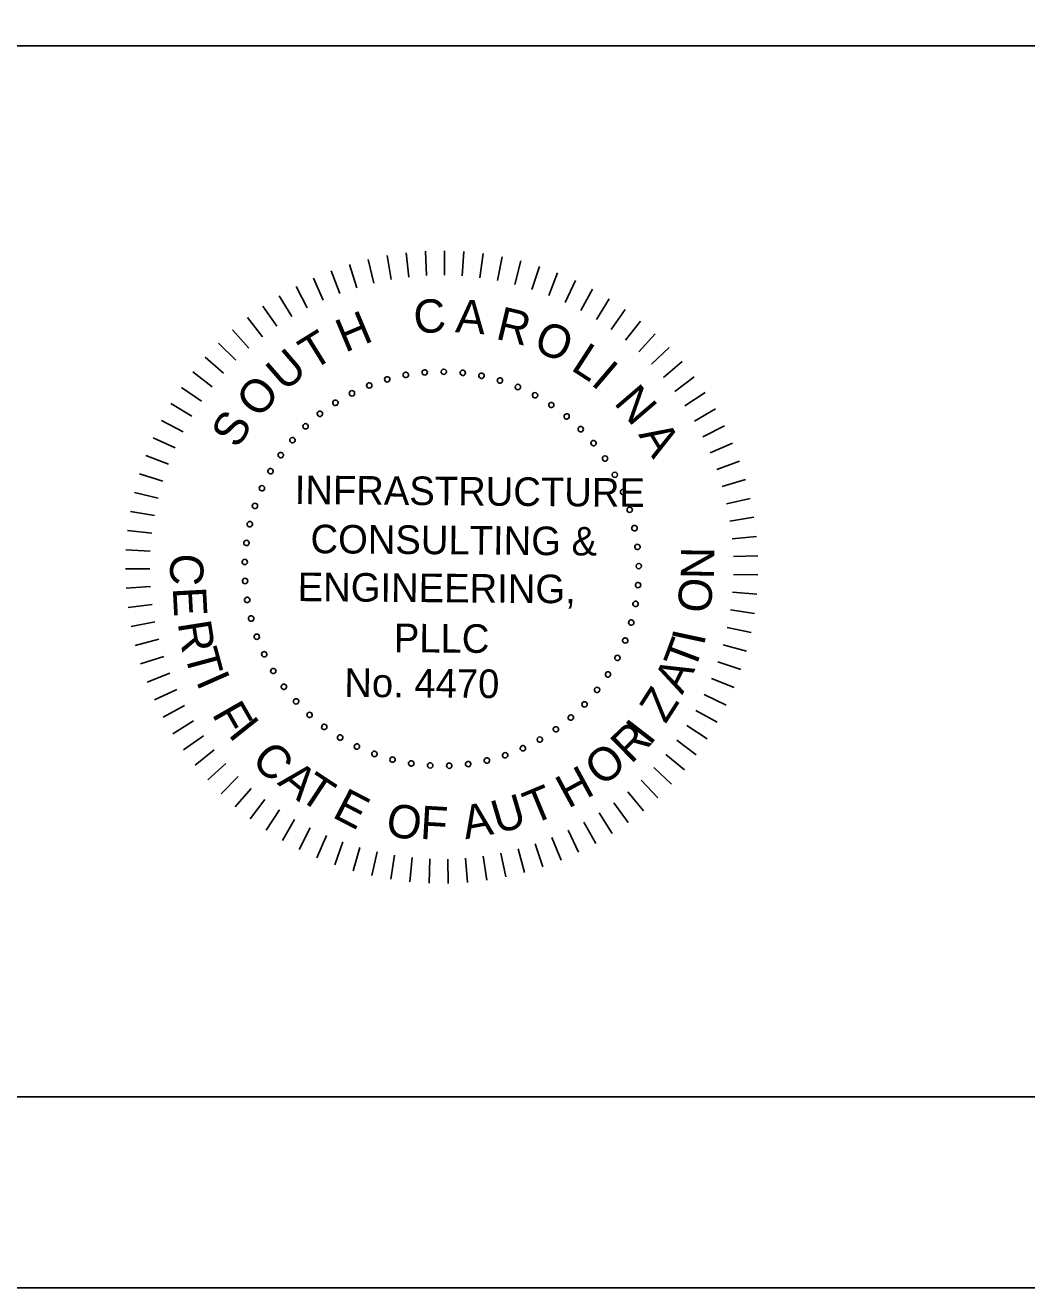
# Model space of a CAD drawing. Extents: x -133.1 to -97, y -1.7 to 20.3.
# Drawn here: x -107.898 to -105.277, y -1.691 to 1.613 of the extents above; entities that cross this region are included whole.
import ezdxf

# ---------------------------------------------------------------- set-up
doc = ezdxf.new("R2010")
doc.units = 0
for name, color, linetype in [('BR_BORDER LINES', 7, 'Continuous'), ('BR_TEXT', 7, 'Continuous'), ('Level 31', 7, 'Continuous')]:
    doc.layers.add(name, color=color, linetype=linetype)

msp = doc.modelspace()

# ---------------------------------------------------------------- linework, layer by layer
at = {"layer": 'BR_BORDER LINES'}
for p, q in [((-110.5071, 1.5591), (-105.1419, 1.5591)), ((-131.3076, -1.191), (-97.6416, -1.191))]:
    msp.add_line(p, q, dxfattribs=at)
at = {"layer": 'BR_TEXT'}
for p, q in [((-107.0007, 0.9998), (-106.9858, 0.9379)), ((-106.9512, 1.01), (-106.9401, 0.9473)), ((-106.9012, 1.0172), (-106.894, 0.9539)), ((-106.8509, 1.0213), (-106.8476, 0.9578)), ((-106.8005, 1.0224), (-106.801, 0.9587)), ((-106.75, 1.0204), (-106.7544, 0.9569)), ((-106.6998, 1.0153), (-106.7081, 0.9522)), ((-106.65, 1.0071), (-106.6621, 0.9446)), ((-106.6007, 0.996), (-106.6166, 0.9343)), ((-107.0972, 0.9704), (-107.0749, 0.9107)), ((-107.0494, 0.9866), (-107.0308, 0.9257)), ((-106.5523, 0.9818), (-106.5719, 0.9213)), ((-106.5048, 0.9648), (-106.528, 0.9055)), ((-107.1895, 0.9295), (-107.1601, 0.873)), ((-107.1439, 0.9513), (-107.1181, 0.8932)), ((-106.4584, 0.9448), (-106.4852, 0.8871)), ((-107.2335, 0.9049), (-107.2008, 0.8503)), ((-106.4133, 0.9221), (-106.4436, 0.8661)), ((-106.3697, 0.8967), (-106.4034, 0.8426)), ((-107.276, 0.8776), (-107.24, 0.8251)), ((-106.3277, 0.8686), (-106.3646, 0.8167)), ((-107.3168, 0.8478), (-107.2776, 0.7976)), ((-106.2875, 0.8381), (-106.3275, 0.7885)), ((-107.3557, 0.8156), (-107.3135, 0.7679)), ((-106.2493, 0.8051), (-106.2922, 0.7581)), ((-107.3925, 0.7811), (-107.3475, 0.736)), ((-106.2131, 0.7699), (-106.2588, 0.7256)), ((-107.4272, 0.7444), (-107.3795, 0.7022)), ((-106.1791, 0.7326), (-106.2275, 0.6911)), ((-107.4595, 0.7056), (-107.4094, 0.6664)), ((-107.4895, 0.665), (-107.437, 0.6289)), ((-106.1475, 0.6932), (-106.1983, 0.6548)), ((-106.1184, 0.652), (-106.1714, 0.6167)), ((-107.5169, 0.6226), (-107.4623, 0.5897)), ((-106.0918, 0.6091), (-106.1469, 0.5771)), ((-107.5416, 0.5786), (-107.4852, 0.5491)), ((-106.0679, 0.5646), (-106.1248, 0.5361)), ((-107.5637, 0.5332), (-107.5055, 0.5072)), ((-106.0467, 0.5188), (-106.1052, 0.4938)), ((-107.5829, 0.4865), (-107.5233, 0.4641)), ((-106.0283, 0.4718), (-106.0883, 0.4504)), ((-107.5992, 0.4387), (-107.5384, 0.42)), ((-106.0129, 0.4237), (-106.0741, 0.406)), ((-107.6126, 0.3901), (-107.5507, 0.3751)), ((-106.0004, 0.3748), (-106.0625, 0.3608)), ((-107.623, 0.3407), (-107.5604, 0.3295)), ((-105.9909, 0.3252), (-106.0538, 0.3151)), ((-107.6304, 0.2907), (-107.5672, 0.2834)), ((-105.9845, 0.2751), (-106.0479, 0.2689)), ((-107.6348, 0.2404), (-107.5712, 0.237)), ((-105.9811, 0.2247), (-106.0448, 0.2224)), ((-107.636, 0.19), (-107.5723, 0.1904)), ((-105.9809, 0.1743), (-106.0445, 0.1758)), ((-107.6342, 0.1395), (-107.5706, 0.1438)), ((-105.9836, 0.1239), (-106.0471, 0.1292)), ((-107.6293, 0.0893), (-107.5661, 0.0974)), ((-105.9895, 0.0737), (-106.0525, 0.0829)), ((-107.6213, 0.0394), (-107.5588, 0.0514)), ((-105.9984, 0.024), (-106.0607, 0.0371)), ((-107.6103, -0.0099), (-107.5487, 0.0059)), ((-106.0103, -0.025), (-106.0717, -0.0082)), ((-107.5964, -0.0584), (-107.5358, -0.0388)), ((-106.0252, -0.0733), (-106.0855, -0.0527)), ((-107.5795, -0.106), (-107.5202, -0.0828)), ((-106.043, -0.1205), (-106.1019, -0.0963)), ((-107.5597, -0.1524), (-107.5019, -0.1256)), ((-106.0636, -0.1666), (-106.1209, -0.1389)), ((-107.5371, -0.1976), (-107.4811, -0.1673)), ((-106.087, -0.2113), (-106.1426, -0.1802)), ((-107.5119, -0.2413), (-107.4578, -0.2077)), ((-106.1131, -0.2545), (-106.1667, -0.22)), ((-107.484, -0.2834), (-107.4321, -0.2465)), ((-106.1418, -0.2961), (-106.1931, -0.2584)), ((-107.4536, -0.3237), (-107.404, -0.2837)), ((-106.173, -0.3358), (-106.2219, -0.2951)), ((-107.4208, -0.362), (-107.3737, -0.3191)), ((-106.2065, -0.3735), (-106.2529, -0.3299)), ((-107.3857, -0.3983), (-107.3413, -0.3527)), ((-106.2423, -0.4092), (-106.2859, -0.3628)), ((-107.3485, -0.4324), (-107.307, -0.3841)), ((-106.2801, -0.4426), (-106.3208, -0.3936)), ((-107.3092, -0.4642), (-107.2708, -0.4135)), ((-106.32, -0.4736), (-106.3576, -0.4222)), ((-107.2681, -0.4935), (-107.2328, -0.4405)), ((-106.3616, -0.5021), (-106.3961, -0.4485)), ((-107.2253, -0.5203), (-107.1933, -0.4652)), ((-107.1809, -0.5444), (-107.1523, -0.4875)), ((-106.4498, -0.5513), (-106.4774, -0.4939)), ((-106.4049, -0.528), (-106.436, -0.4725)), ((-107.1352, -0.5657), (-107.1101, -0.5072)), ((-107.0882, -0.5842), (-107.0668, -0.5243)), ((-106.4959, -0.5718), (-106.52, -0.5128)), ((-107.0402, -0.5998), (-107.0225, -0.5387)), ((-106.9913, -0.6125), (-106.9773, -0.5504)), ((-106.9418, -0.6221), (-106.9316, -0.5593)), ((-106.6903, -0.6245), (-106.6995, -0.5615)), ((-106.6406, -0.6158), (-106.6536, -0.5535)), ((-106.5915, -0.6041), (-106.6083, -0.5427)), ((-106.5432, -0.5894), (-106.5637, -0.5291)), ((-106.8918, -0.6288), (-106.8854, -0.5654)), ((-106.8414, -0.6323), (-106.8389, -0.5687)), ((-106.7909, -0.6328), (-106.7923, -0.5691)), ((-106.7405, -0.6302), (-106.7458, -0.5667))]:
    msp.add_line(p, q, dxfattribs=at)
for centre, start, end in [((-106.9021, 0.6977), 10.6038, 190.6038), ((-106.9021, 0.6977), 190.6038, 10.6038), ((-106.8527, 0.7043), 5.0653, 185.0653), ((-106.8527, 0.7043), 185.0653, 5.0653), ((-106.8029, 0.7062), 359.5268, 179.5268), ((-106.8029, 0.7062), 179.5268, 359.5268), ((-106.7531, 0.7033), 173.9884, 353.9884), ((-106.7531, 0.7033), 353.9884, 173.9884), ((-106.7039, 0.6956), 168.4499, 348.4499), ((-106.7039, 0.6956), 348.4499, 168.4499), ((-106.9977, 0.6702), 21.6807, 201.6807), ((-106.9977, 0.6702), 201.6807, 21.6807), ((-106.9506, 0.6862), 16.1422, 196.1422), ((-106.9506, 0.6862), 196.1422, 16.1422), ((-106.6557, 0.6832), 162.9114, 342.9114), ((-106.6557, 0.6832), 342.9114, 162.9114), ((-106.6088, 0.6662), 157.373, 337.373), ((-106.6088, 0.6662), 337.373, 157.373), ((-107.0864, 0.6248), 32.7576, 212.7576), ((-107.0864, 0.6248), 212.7576, 32.7576), ((-107.0431, 0.6496), 27.2191, 207.2191), ((-107.0431, 0.6496), 207.2191, 27.2191), ((-106.5639, 0.6447), 151.8345, 331.8345), ((-106.5639, 0.6447), 331.8345, 151.8345), ((-107.127, 0.5959), 38.2961, 218.2961), ((-107.127, 0.5959), 218.2961, 38.2961), ((-106.5212, 0.619), 146.2961, 326.2961), ((-106.5212, 0.619), 326.2961, 146.2961), ((-106.4811, 0.5893), 320.7576, 140.7576), ((-107.1646, 0.5633), 43.8345, 223.8345), ((-107.1646, 0.5633), 223.8345, 43.8345), ((-106.4811, 0.5893), 140.7576, 320.7576), ((-106.4442, 0.5559), 315.2191, 135.2191), ((-107.1989, 0.5271), 49.373, 229.373), ((-107.1989, 0.5271), 229.373, 49.373), ((-106.4442, 0.5559), 135.2191, 315.2191), ((-106.4106, 0.5191), 129.6807, 309.6807), ((-106.4106, 0.5191), 309.6807, 129.6807), ((-107.2296, 0.4879), 54.9114, 234.9114), ((-107.2296, 0.4879), 234.9114, 54.9114), ((-106.3808, 0.4792), 124.1422, 304.1422), ((-106.3808, 0.4792), 304.1422, 124.1422), ((-107.2563, 0.4458), 60.4499, 240.4499), ((-107.2563, 0.4458), 240.4499, 60.4499), ((-106.3549, 0.4366), 118.6038, 298.6038), ((-106.3549, 0.4366), 298.6038, 118.6038), ((-107.2788, 0.4014), 65.9884, 245.9884), ((-107.2788, 0.4014), 245.9884, 65.9884), ((-106.3333, 0.3917), 113.0653, 293.0653), ((-106.3333, 0.3917), 293.0653, 113.0653), ((-107.297, 0.3549), 71.5268, 251.5268), ((-107.297, 0.3549), 251.5268, 71.5268), ((-106.3161, 0.3449), 107.5268, 287.5268), ((-106.3161, 0.3449), 287.5268, 107.5268), ((-107.3106, 0.307), 77.0653, 257.0653), ((-107.3106, 0.307), 257.0653, 77.0653), ((-106.3035, 0.2967), 101.9884, 281.9884), ((-106.3035, 0.2967), 281.9884, 101.9884), ((-107.3195, 0.258), 82.6038, 262.6038), ((-107.3195, 0.258), 262.6038, 82.6038), ((-106.2956, 0.2475), 96.4499, 276.4499), ((-106.2956, 0.2475), 276.4499, 96.4499), ((-107.3236, 0.2083), 88.1422, 268.1422), ((-107.3236, 0.2083), 268.1422, 88.1422), ((-106.2925, 0.1977), 90.9114, 270.9114), ((-106.2925, 0.1977), 270.9114, 90.9114), ((-107.3229, 0.1585), 93.6807, 273.6807), ((-107.3229, 0.1585), 273.6807, 93.6807), ((-106.2942, 0.1479), 85.373, 265.373), ((-106.2942, 0.1479), 265.373, 85.373), ((-107.3174, 0.109), 99.2191, 279.2191), ((-107.3174, 0.109), 279.2191, 99.2191), ((-106.3007, 0.0985), 79.8345, 259.8345), ((-106.3007, 0.0985), 259.8345, 79.8345), ((-107.3071, 0.0602), 104.7576, 284.7576), ((-107.3071, 0.0602), 284.7576, 104.7576), ((-106.312, 0.05), 74.2961, 254.2961), ((-106.312, 0.05), 254.2961, 74.2961), ((-107.2922, 0.0126), 110.2961, 290.2961), ((-107.2922, 0.0126), 290.2961, 110.2961), ((-106.3279, 0.0028), 68.7576, 248.7576), ((-106.3279, 0.0028), 248.7576, 68.7576), ((-107.2728, -0.0332), 115.8345, 295.8345), ((-107.2728, -0.0332), 295.8345, 115.8345), ((-106.3483, -0.0427), 63.2191, 243.2191), ((-106.3483, -0.0427), 243.2191, 63.2191), ((-107.249, -0.077), 121.373, 301.373), ((-107.249, -0.077), 301.373, 121.373), ((-106.3729, -0.086), 57.6807, 237.6807), ((-106.3729, -0.086), 237.6807, 57.6807), ((-107.2211, -0.1183), 126.9114, 306.9114), ((-107.2211, -0.1183), 306.9114, 126.9114), ((-106.4016, -0.1267), 52.1422, 232.1422), ((-106.4016, -0.1267), 232.1422, 52.1422), ((-107.1894, -0.1567), 132.4499, 312.4499), ((-107.1894, -0.1567), 312.4499, 132.4499), ((-106.4342, -0.1645), 46.6038, 226.6038), ((-106.4342, -0.1645), 226.6038, 46.6038), ((-107.1541, -0.1919), 137.9884, 317.9884), ((-107.1541, -0.1919), 317.9884, 137.9884), ((-106.4702, -0.1989), 41.0653, 221.0653), ((-106.4702, -0.1989), 221.0653, 41.0653), ((-107.1156, -0.2235), 143.5268, 323.5268), ((-107.1156, -0.2235), 323.5268, 143.5268), ((-106.5093, -0.2297), 35.5268, 215.5268), ((-106.5093, -0.2297), 215.5268, 35.5268), ((-107.0742, -0.2512), 149.0653, 329.0653), ((-107.0742, -0.2512), 329.0653, 149.0653), ((-106.5513, -0.2566), 29.9884, 209.9884), ((-106.5513, -0.2566), 209.9884, 29.9884), ((-107.0303, -0.2749), 154.6038, 334.6038), ((-107.0303, -0.2749), 334.6038, 154.6038), ((-106.9843, -0.2941), 160.1422, 340.1422), ((-106.9843, -0.2941), 340.1422, 160.1422), ((-106.642, -0.2976), 18.9114, 198.9114), ((-106.642, -0.2976), 198.9114, 18.9114), ((-106.5957, -0.2793), 24.4499, 204.4499), ((-106.5957, -0.2793), 204.4499, 24.4499), ((-106.9367, -0.3089), 165.6807, 345.6807), ((-106.9367, -0.3089), 345.6807, 165.6807), ((-106.8879, -0.3189), 171.2191, 351.2191), ((-106.8879, -0.3189), 351.2191, 171.2191), ((-106.8384, -0.3242), 356.7576, 176.7576), ((-106.8384, -0.3242), 176.7576, 356.7576), ((-106.7885, -0.3248), 2.2961, 182.2961), ((-106.7885, -0.3248), 182.2961, 2.2961), ((-106.7389, -0.3205), 7.8345, 187.8345), ((-106.7389, -0.3205), 187.8345, 7.8345), ((-106.6899, -0.3114), 13.373, 193.373), ((-106.6899, -0.3114), 193.373, 13.373)]:
    msp.add_arc(centre, 0.00701, start, end, dxfattribs=at)
at = {"layer": 'Level 31'}
msp.add_lwpolyline([(-133.1409, -1.691), (-97.141, -1.691), (-97.141, 20.309), (-133.1409, 20.309)], close=True, dxfattribs=at)

# ---------------------------------------------------------------- texts
at = {"layer": 'BR_TEXT'}
for s, height, rotation, p in [('C', 0.0872, 4.7281, (-106.8784, 0.8048)), ('A', 0.0872, 355.6981, (-106.7739, 0.8098)), ('H', 0.0872, 22.7882, (-107.0612, 0.7554)), ('R', 0.0872, 346.6681, (-106.6696, 0.7928)), ('O', 0.0872, 337.638, (-106.5719, 0.763)), ('T', 0.0872, 31.8182, (-107.1461, 0.7078)), ('U', 0.0872, 40.8482, (-107.2194, 0.6516)), ('L', 0.0872, 327.108, (-106.4731, 0.7125)), ('I', 0.0872, 319.578, (-106.4205, 0.6747)), ('O', 0.0872, 49.8782, (-107.2864, 0.5806)), ('N', 0.0872, 310.548, (-106.3597, 0.6239)), ('S', 0.0872, 58.9083, (-107.3418, 0.5024)), ('A', 0.0872, 301.5179, (-106.2946, 0.5415)), ('INFRASTRUCTURE', 0.074771, 359.5268, (-107.1932, 0.3599)), ('CONSULTING &', 0.074771, 359.5268, (-107.1519, 0.2313)), ('N', 0.0872, 89.2085, (-106.0953, 0.1628)), ('C', 0.0872, 267.025, (-107.5168, 0.2325)), ('ENGINEERING,', 0.074771, 359.5268, (-107.1855, 0.1059)), ('E', 0.0872, 273.025, (-107.5124, 0.1409)), ('O', 0.0872, 83.2085, (-106.1064, 0.0713)), ('R', 0.0872, 279.025, (-107.4996, 0.0487)), ('PLLC', 0.07477, 359.5268, (-106.9338, -0.0277)), ('T', 0.0872, 69.3954, (-106.1476, -0.0805)), ('I', 0.0872, 77.9093, (-106.1219, -0.013)), ('T', 0.0872, 285.025, (-107.4822, -0.0301)), ('A', 0.0872, 63.3954, (-106.1784, -0.1408)), ('I', 0.0872, 293.7713, (-107.4525, -0.1032)), ('No. 4470', 0.07477, 359.5268, (-107.0633, -0.1446)), ('Z', 0.0872, 57.3954, (-106.2222, -0.2172)), ('F', 0.0872, 299.7713, (-107.4113, -0.1893)), ('I', 0.0872, 308.5268, (-107.3692, -0.2431)), ('R', 0.0872, 44.5268, (-106.3127, -0.3221)), ('I', 0.0872, 52.3339, (-106.2633, -0.2748)), ('C', 0.0872, 314.5268, (-107.3099, -0.3133)), ('O', 0.0872, 38.5268, (-106.3893, -0.3821)), ('A', 0.0872, 320.5268, (-107.2407, -0.3718)), ('H', 0.0872, 28.5268, (-106.4774, -0.4381)), ('T', 0.0872, 326.5268, (-107.1863, -0.4103)), ('E', 0.0872, 332.5268, (-107.0977, -0.4581)), ('T', 0.0872, 22.5268, (-106.5706, -0.4799)), ('O', 0.0872, 350.5268, (-106.9576, -0.507)), ('A', 0.0872, 10.5268, (-106.7462, -0.5177)), ('U', 0.0872, 16.5268, (-106.6623, -0.5042)), ('F', 0.0872, 356.5268, (-106.8661, -0.5161))]:
    msp.add_text(s, height=height, rotation=rotation, dxfattribs=at).set_placement(p)

doc.saveas('drawing.dxf')
